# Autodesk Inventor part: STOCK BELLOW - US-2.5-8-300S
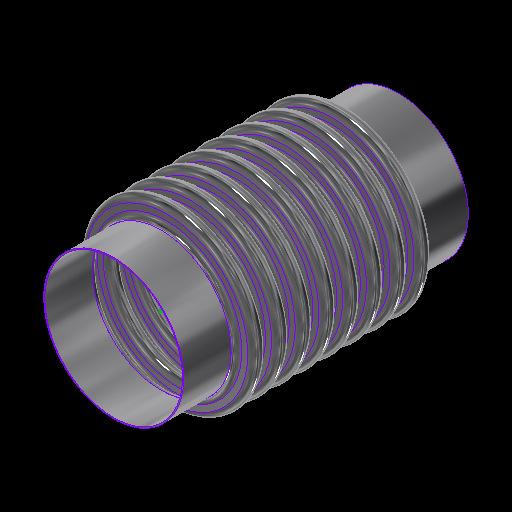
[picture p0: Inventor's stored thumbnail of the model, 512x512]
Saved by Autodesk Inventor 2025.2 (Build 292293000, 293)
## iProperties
Category: 24 GA (0.024 THICK)
RuleStatus: InUse
Created: 2024-01
Part Number: STOCK BELLOW - US-2.5-8-300S
Project: =STOCK BELLOWS: <Stock Number><SFILL>
Material: ASTM A240-304
Description: =STOCK BELLOWS: <Stock Number>, <SID_> I.D., <SOD_> O.D., <SPLY_> PLY, <Category>, <SNET_CONS> CONS.<PITCH_><STANGENT_> TANGENT<SFILL>
Document SubType Name: Sheet Metal
Designer: GS
Stock Number: U.S-2.5-8-300S
Surface Area: 1355.78 cm^2
Volume: 41.0641 cm^3
Sheet Metal Rule: Default
Appearance: STAINLESS STEEL
Mass: 330.865 g
Density: 8.05729 g/cm^3
THK: 0.036
ID: 3.500
OD: 4.250
CONS_: 2
PITCH: 0.500
TANGENT: 0.500
BELLOWS_UPSET: 0.000
d79: 1.000
d82: 1.000
d83: 26.000
d84: 24.000
d174: 8
d214: 8
STHK_: 0.024
SID_: 2.900
SOD_: 3.700
SPITCH_: 0.500
STANGENT__: 1.000
SBELLOWS_UPSET_: 0.000
SDIFF_TAN: 1.000
d252: 2
d275: 2
d287: 0.050
d289: 0.500
d290: 0.000
SOD_NECK: 2 15/16
PLY: 1
PSET: 4.178
PBAR: 1.035
COUNTER: 1.500
NET_TUBE: 3.071
CONS: 2
S_CONS: 0
NET_CONS: 2
ID_M: 88.90 mm
OD_M: 107.95 mm
THK_M: 0.91 mm
ID_U: 3.500 in
OD_U: 4.250 in
THK_U: 0.036 in
TANGENT2: 0.500
TAN_TO_TAN: 1.000 in
d80: 2.571
d81: 10
SID: 2.375
SCONS_: 8
SPITCH: 0.250
STANGENT_: 1.000
SBELLOWS_UPSET: 0.000
SNET_CONS: 8
SS_CONS: 0
SCONS: 8
d190: 8
d191: 1
d192: 1
d193: 8
d194: 0
SIZE: 2.50
PRESSURE: 300
d230: 8
STANGENT: 4.000
SPLY_: 1
d233: 8
d234: 0
d263: 2
d265: 1
d268: 2
d269: 0
d286: 2
d288: 1
d291: 2
d292: 0
SREROLL: 0.750
BLETP: 0.000 ul
PRES_Copy: 85
MATTABLE: 20 GA (0.036 THICK)
PART_NUMBER: U.S-2.5-8-300S
PITCH_: =, <SPITCH_> PITCH,
CFILL: .
SFILL: .
MESH: ,
COMP: 0.77
EXT: 0.39
LAT: 0.30
ANG: 573
ASR: 1441
LSR: 1471
ANSR: 53
PRES: 300
COMPM: 7.7
EXTM: 3.85
LATM: 3.00
ASRM: 252.362
PRESM: 20.684
LSRM: 257.616
ANSRM: 9.282
TEMPMIN: 20
TEMPMAX: 800
TEMPMINM: -7
TEMPMAXM: 427
WEIGHTM: 0.331
WEIGHT: 0.729
Author: GS
Keywords: 20 GA (0.036 THICK)
Comments: =STOCK BELLOW - <STOCK NUMBER>
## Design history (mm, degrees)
sketch "Sketch2"
  geometry: L1 (0, -177.245)-(0, 562.856) reference; L2 (45.364, 0)-(44.45, 0); L3 (48.082, -2.718)-(50.343, -2.718); L4 (48.082, -3.632)-(50.343, -3.632); L5 (50.343, -9.982)-(48.082, -9.982); L6 (50.343, -9.068)-(48.082, -9.068); L7 (45.364, -12.7)-(44.45, -12.7); L8 (48.082, 0)-(48.082, -12.7); L9 (50.343, -6.35)-(53.975, -6.35); L10 (44.45, 0)-(44.45, -12.7); L11 (20.376, 102.841)-(20.376, 101.926); L12 (58.262, 457.127)-(58.262, 349.177); L13 (58.262, 444.427)-(58.262, 336.477); L14 (93.133, -58.817)-(93.133, -71.517); L15 (118.746, -66.401)-(118.746, -66.401); L16 (50.343, -9.068)-(50.343, -9.982); L17 (48.082, -9.068)-(48.082, -9.982); L18 (48.082, -9.525)-(50.343, -9.525); L19 (53.975, 0)-(53.975, -12.7); L20 (-50.343, -9.068)-(-50.343, -9.982); L21 (-50.343, -2.718)-(-48.082, -2.718); L22 (-50.343, -3.632)-(-48.082, -3.632); L23 (-48.082, -9.068)-(-50.343, -9.068); L24 (-50.343, -9.525)-(-48.082, -9.525); L25 (-48.082, -9.982)-(-50.343, -9.982); L26 (-48.082, -9.068)-(-48.082, -9.982); L27 (-44.45, 0.653)-(-44.45, -12.047); L28 (-48.082, -6.35)-(-44.45, -6.35); L29 (-50.343, 0.653)-(-50.343, -12.7); L30 (-53.061, 0)-(-53.975, 0); L31 (-53.975, 0)-(-53.975, -12.7); L32 (-53.061, -12.7)-(-53.975, -12.7); A1 r 2.718 centre (48.082, 0) between (45.364, 0) and (48.082, -2.718); A2 r 3.632 centre (48.082, 0) between (44.45, 0) and (48.082, -3.632); A3 r 3.632 centre (50.343, -6.35) between (50.343, -9.982) and (50.343, -2.718); A4 r 2.718 centre (50.343, -6.35) between (50.343, -9.068) and (50.343, -3.632); A5 r 2.718 centre (48.082, -12.7) between (48.082, -9.982) and (45.364, -12.7); A6 r 3.632 centre (48.082, -12.7) between (48.082, -9.068) and (44.45, -12.7); A7 r 3.175 centre (50.343, -6.35) between (50.343, -9.525) and (53.518, -6.35); A8 r 3.175 centre (48.082, -12.7) between (48.082, -9.525) and (44.907, -12.7); A9 r 2.718 centre (-50.343, -12.7) between (-50.343, -9.982) and (-53.061, -12.7); A10 r 2.718 centre (-48.082, -6.35) between (-48.082, -9.068) and (-48.082, -3.632); A11 r 3.175 centre (-48.082, -6.35) between (-48.082, -9.525) and (-44.907, -6.35); A12 r 3.632 centre (-48.082, -6.35) between (-48.082, -9.982) and (-48.082, -2.718); A13 r 3.175 centre (-50.343, -12.7) between (-50.343, -9.525) and (-53.518, -12.7); A14 r 3.632 centre (-50.343, -12.7) between (-50.343, -9.068) and (-53.975, -12.7); A15 r 2.718 centre (-50.343, 0) between (-53.061, 0) and (-50.343, -2.718); A16 r 3.632 centre (-50.343, 0) between (-53.975, 0) and (-50.343, -3.632); 10 further points
  constraints: 62 end point, 38 point on circle, 20 tangent, 16 centre point, 12 parallel, 9 midpoint, 7 vertical, 6 coincident, 6 concentric, 6 point on line, 4 equal radius, 4 perpendicular, 3 horizontal, 1 collinear, 1 horizontal alignment, 10 other
  dimensions: "THK" = 0.9144 distance of L11.start L11.end; "ID" = 88.9 distance of L11.end point (20.376, 13.026); "OD" = 107.95 distance of L12.start L12.end; "PITCH" = 12.7 distance of L12.start L13.start; "TANGENT" = 12.7 distance of L14.start L14.end; "BELLOWS_UPSET" = 0 distance of L15.start L15.end; "d43" = 88.9 diameter of L10 L1 (= ID); "d44" = 107.95 diameter of L9.end L1 (= OD); "d45" = 0.9144 distance between parallel lines of L5 L6 (computed from THK, PLY); "d46" = 3.6322 radius of A3 (computed from PITCH, THK, PLY); "UPSET_PITCH" = 12.7 distance of L2.end L7.end (derived); "SIDEWALL_ANGLE" = 360 deg dimension on L3 L9 (derived); "CON_GAP" = 5.4356 distance of point (48.082, -9.068) point (48.082, -3.632) (derived); "TAN1" = 4.98728 dimension on A8 (derived); "TAN2" = 4.98728 dimension on A7 (derived); "LEG1" = 2.2606 distance of L18.start L18.end (derived); "d278" = 0.9144 distance between parallel lines of L25 L23 (derived); "d279" = 3.6322 radius of A12 (derived); "d280" = 12.7 distance of L30.end L31.end (derived); "d281" = 360 deg dimension on L21 L28 (derived); "d282" = 5.4356 distance of point (-50.343, -9.068) point (-50.343, -3.632) (derived); "d283" = 4.98728 dimension on A13 (derived); "d284" = 4.98728 dimension on A11 (derived); "d285" = 2.2606 distance of L24.start L24.end (derived); "d293" = 88.9 diameter of L27 L1 (derived); "d294" = 107.95 diameter of L31 L1 (derived)
  node "Sketch Rectangular Pattern1" dims "d31" = 25.4, "ID" = 88.9
  node "Sketch Rectangular Pattern2" dims "d39" = 25.4, "PITCH" = 12.7
revolve "CONS" stored, may be unused: angle "d48" = 90 deg
node "BELLOW MIDPLANE"
pattern_linear "Rectangular Pattern2" dims "d52" = 12.7 (= UPSET_PITCH)
sketch "Sketch5"
  geometry: C1 r 45.364 at (0, 0) reference; C2 r 44.45 at (0, 0) reference
extrude "TANGENT" new body sketch "Sketch5" distance "d53" = 12.7 (= TANGENT); taper "d54" = 0 deg
revolve "SAMETAN" stored, may be unused: angle "d65" = 90 deg
revolve "DIFFTAN" stored, may be unused: angle "d70" = 90 deg
sketch "Sketch9"
  geometry: L1 (53.319, 0)-(-53.319, 0) reference; L2 (0, -17.78)-(0, 17.78) reference; L3 (38.085, 0)-(-38.085, 0); L4 (38.085, -11.906)-(38.085, 11.906); L5 (25.385, -11.906)-(25.385, 11.906); L6 (13.15, 11.906)-(13.15, -11.906); L7 (-25.385, -11.906)-(-25.385, 11.906); L8 (-38.085, -11.906)-(-38.085, 11.906); L9 (37.291, -11.906)-(37.291, 11.906); L10 (38.085, -11.906)-(37.291, -11.906); L11 (38.085, 11.906)-(37.291, 11.906); L12 (13.546, 11.906)-(12.753, 11.906); L13 (12.753, 11.906)-(12.753, -11.906); L14 (12.753, -11.906)-(13.546, -11.906); L15 (13.546, -11.906)-(13.546, 11.906); L16 (-13.546, 11.906)-(-13.546, -11.906); L17 (-13.15, 11.906)-(-13.15, -11.906); L18 (-13.546, -11.906)-(-12.753, -11.906); L19 (-12.753, -11.906)-(-12.753, 11.906); L20 (-12.753, 11.906)-(-13.546, 11.906); L21 (-38.085, -11.906)-(-37.291, -11.906); L22 (-37.291, -11.906)-(-37.291, 11.906); L23 (-37.291, 11.906)-(-38.085, 11.906); L24 (-38.085, 11.906)-(-38.085, -11.906); L25 (38.085, -0.397)-(-38.085, -0.397); L26 (-38.085, -0.397)-(-38.085, 0.397); L27 (-38.085, 0.397)-(38.085, 0.397); L28 (38.085, 0.397)-(38.085, -0.397); L29 (-38.085, 11.906)-(38.085, 11.906); L30 (38.085, 11.906)-(38.085, 12.7); L31 (38.085, 12.7)-(-38.085, 12.7); L32 (-38.085, 12.7)-(-38.085, 11.906); L33 (38.085, -11.906)-(-38.085, -11.906); L34 (-38.085, -11.906)-(-38.085, -12.7); L35 (-38.085, -12.7)-(38.085, -12.7); L36 (38.085, -12.7)-(38.085, -11.906); 30 further points
  constraints: 68 end point, 13 midpoint, 13 parallel, 8 horizontal, 7 perpendicular, 6 equal length, 3 point on line, 2 vertical, 14 other
  dimensions: "d115" = 23.8125 distance of L4.start L4.end (derived); "d116" = 12.7 distance between parallel lines of L4 L5 (derived); "d117" = 12.23516 distance between parallel lines of L5 L6 (derived); "d125" = 38.53427 distance between parallel lines of L7 L6 (derived); "d127" = 12.7 distance between parallel lines of L8 L7 (derived); "d128" = 24.93516 distance between parallel lines of L6 L4 (derived); "d130" = 76.16943 distance between parallel lines of L8 L4 (derived); "RULER_THK" = 0.79375 distance between parallel lines of L4 L9; "d135" = 0.79375 distance of L13.end L14.end (derived); "d138" = 26.29911 distance of L13.end L16.end (derived); "d143" = 0.79375 distance of L22.end L8.end (derived); "d144" = 0.79375 distance between parallel lines of L27 L25 (derived)
extrude "RULER" join sketch "Sketch9" distance "d149" = 0.79375 (derived); taper "d150" = 0 deg
extrude "BARS" join sketch "Sketch9" distance "d151" = 0.79375 (derived); taper "d152" = 0 deg
pattern_linear "Rectangular Pattern4" dims "d155" = 26.29911 (derived)
sketch "Sketch13"
  geometry: L1 (93.149, -52.467)-(93.149, -77.867); L2 (37.44, 0)-(36.83, 0); L3 (37.44, -12.7)-(36.83, -12.7); L4 (43.51, -9.83)-(40.31, -9.83); L5 (43.51, -9.22)-(40.31, -9.22); L6 (43.51, -6.35)-(46.99, -6.35); L7 (40.31, -2.87)-(43.51, -2.87); L8 (40.31, 0)-(40.31, -12.7); L9 (36.83, 0)-(36.83, -12.7); L10 (58.254, -402.451)-(58.254, -496.431); L11 (58.254, -415.151)-(58.254, -509.131); L12 (58.254, -440.551)-(58.254, -534.531); L13 (58.254, -453.251)-(58.254, -547.231); L14 (58.254, -465.951)-(58.254, -559.931); L15 (58.254, -478.651)-(58.254, -572.631); L16 (58.254, -491.351)-(58.254, -585.331); L17 (58.254, -427.851)-(58.254, -521.831); L18 (20.376, 102.536)-(20.376, 101.926); L19 (40.31, -3.48)-(43.51, -3.48); L20 (0, -722.904)-(0, 240.109) reference; L21 (-23.752, 0)-(142.514, 0) reference; A1 r 2.87 centre (40.31, 0) between (37.44, 0) and (40.31, -2.87); A2 r 2.87 centre (40.31, -12.7) between (40.31, -9.83) and (37.44, -12.7); A3 r 3.48 centre (40.31, -12.7) between (40.31, -9.22) and (36.83, -12.7); A4 r 2.87 centre (43.51, -6.35) between (43.51, -9.22) and (43.51, -3.48); A5 r 3.48 centre (43.51, -6.35) between (43.51, -9.83) and (43.51, -2.87); A6 r 3.48 centre (40.31, 0) between (36.83, 0) and (40.31, -3.48); 6 further points; 1 other entity
  constraints: 38 end point, 15 point on circle, 9 tangent, 6 centre point, 6 parallel, 5 vertical alignment, 4 point on line, 4 vertical, 3 coincident, 3 concentric, 2 collinear, 2 equal radius, 1 horizontal, 1 perpendicular, 23 other
  dimensions: "SBELLOWS_UPSET_" = 0 distance of point (118.762, -66.401) point (118.762, -66.401); "STOTAL_THK_BELLOW__" = 0.6096 distance between parallel lines of L4 L5 (derived); "d224" = 3.4798 radius of A5 (derived); "d225" = 12.7 distance of L2.end L3.end (derived); "SSIDEWALL_ANGLE_" = 0 deg angle of L7 L6 (derived); "SSCON_GAP_" = 5.7404 distance of point (40.31, -9.22) point (40.31, -3.48) (derived); "d235" = 73.66 diameter of L9 L20 (derived); "d236" = 93.98 diameter of L6.end L20 (derived)
  node "Sketch Rectangular Pattern4" dims "d228" = 25.4
  node "Sketch Rectangular Pattern5" dims "d229" = 25.4
revolve "SBELLOW" stored, may be unused: angle "d197" = 90 deg
pattern_linear "Rectangular Pattern5" dims "d204" = 12.7 (derived)
revolve "STANGENT" stored, may be unused: angle "d240" = 90 deg
revolve "SSAMETAN" stored, may be unused: angle "d241" = 90 deg
revolve "SDIFFTAN" stored, may be unused: angle "d246" = 90 deg
revolve "INVCON" stored, may be unused: angle "d295" = 90 deg
pattern_linear "Rectangular Pattern6" dims "d298" = 12.7 (derived)
revolve "INVTANGENT" stored, may be unused: angle "d302" = 90 deg
revolve "INVSAMETAN" stored, may be unused: angle "d307" = 90 deg
revolve "INVDIFFTAN" stored, may be unused: angle "d312" = 90 deg
sketch "ID BELLOW MOUNT CALC"
  geometry: L1 (44.45, 0)-(38.1, 0); L2 (38.1, 0)-(38.1, 12.7); L3 (38.1, 12.7)-(44.45, 12.7); L4 (44.45, 12.7)-(44.45, 0); L5 (36.513, 12.7)-(35.598, 12.7); L6 (35.598, 12.7)-(35.598, 0); L7 (35.598, 0)-(36.513, 0); L8 (36.513, 0)-(36.513, 12.7); L9 (0, -2.54)-(0, 15.24) reference; L10 (-8.89, 0)-(53.34, 0) reference; 1 further point
  constraints: 16 end point, 5 parallel, 2 collinear, 2 horizontal, 2 perpendicular
  dimensions: "d314" = 12.7 distance of L5.end L6.end (derived); "d315" = 0.9144 distance of L5.start L5.end (derived); "IG" = 1.5875 distance between parallel lines of L2 L8; "PIPE_OD" = 88.9 diameter of L4 L9; "PIPE_WALL" = 6.35 distance of L2.end L3.end; "ID_MT_BELLOW" = 71.1962 diameter of L6 L9 (derived)
revolve "CFILL" stored, may be unused: angle "d320" = 90 deg
pattern_linear "Rectangular Pattern7" dims "d323" = 12.7 (derived)
revolve "SFILL" stored, may be unused: angle "d324" = 90 deg
pattern_linear "Rectangular Pattern8" dims "d327" = 12.7 (derived)
node "STOCK BELLOW MIDPLANE"
node "BELLOW"
sketch "Sketch6"
  geometry: L1 (-12.7, 45.364)-(0, 45.364); L2 (0, 45.364)-(0, 44.45); L3 (0, 44.45)-(-12.7, 44.45); L4 (-12.7, 44.45)-(-12.7, 45.364); L5 (10.16, 0)-(-60.96, 0) reference; L6 (-38.1, -89.422)-(-38.1, 153.44) reference; 1 further point
  constraints: 8 end point, 2 parallel, 1 horizontal, 1 perpendicular
  dimensions: "d61" = 12.7 distance of L2.end L3.end (derived); "d62" = 0.9144 distance of L1.end L2.end (derived); "d63" = 88.9 diameter of L3 L5 (derived); "d64" = 25.4 distance between parallel lines of L4 L6 (derived)
sketch "Sketch12"
  geometry: 1 further point
sketch "Sketch14"
  geometry: L1 (-25.4, 37.44)-(0, 37.44); L2 (0, 37.44)-(0, 36.83); L3 (0, 36.83)-(-25.4, 36.83); L4 (-25.4, 36.83)-(-25.4, 37.44); L5 (5.08, 0)-(-30.48, 0) reference; L6 (0, -8.89)-(0, 53.34) reference; 1 further point
  constraints: 8 end point, 2 parallel, 1 collinear, 1 horizontal, 1 perpendicular
  dimensions: "d237" = 0.6096 distance of L3.end L1.start (derived); "d238" = 73.66 diameter of L3 L5 (derived); "d239" = 25.4 distance of L1.start L1.end (derived); "SOD_NECK" = 74.8792 diameter of L1 L5 (derived)
sketch "Sketch15"
  geometry: L1 (-8.89, 0)-(53.34, 0) reference; L2 (36.83, -101.6)-(37.44, -101.6); L3 (37.44, -101.6)-(37.44, -127); L4 (37.44, -127)-(36.83, -127); L5 (36.83, -127)-(36.83, -101.6); L6 (0, -154.94)-(0, 40.64) reference; 1 further point
  constraints: 8 end point, 2 parallel, 1 horizontal, 1 perpendicular
  dimensions: "d205" = 25.4 distance of L4.end L2.start (derived); "d206" = 0.6096 distance of L3.end L4.end (derived); "d207" = 73.66 diameter of L5 L6 (derived); "d208" = 101.6 distance between parallel lines of L1 L2 (derived)
node "TANGENT_"
node "SAME_TAN"
sketch "Sketch8"
  geometry: L1 (45.364, -25.4)-(44.45, -25.4); L2 (44.45, -25.4)-(44.45, -38.1); L3 (44.45, -38.1)-(45.364, -38.1); L4 (45.364, -38.1)-(45.364, -25.4); L5 (0, -48.26)-(0, 22.86) reference; L6 (-89.422, 0)-(153.44, 0) reference; 1 further point
  constraints: 8 end point, 2 parallel, 1 horizontal, 1 perpendicular
  dimensions: "d66" = 88.9 diameter of L2 L5 (derived); "TOTAL_THK_BELLOW" = 0.9144 distance of L2.end L3.end (derived); "d68" = 25.4 distance between parallel lines of L1 L6 (derived); "d69" = 12.7 distance of L1.end L2.end (derived)
node "DIFF_TAN"
node "Sketch Rectangular Pattern3" dims "d138" = 26.29911 (derived), "d141" = 25.4
node "SBELLOW_"
node "STANGENT_"
node "SSAME_TAN"
sketch "Sketch16"
  geometry: L1 (37.44, -101.6)-(36.83, -101.6); L2 (36.83, -101.6)-(36.83, -127); L3 (36.83, -127)-(37.44, -127); L4 (37.44, -127)-(37.44, -101.6); L5 (0, -154.94)-(0, 40.64) reference; L6 (-8.89, 0)-(53.34, 0) reference; 1 further point
  constraints: 8 end point, 2 parallel, 1 horizontal, 1 perpendicular
  dimensions: "SDIFF_TAN" = 25.4 distance of L3.end L1.start; "d243" = 0.6096 distance of L2.end L3.end (derived); "d244" = 101.6 distance between parallel lines of L1 L6 (derived); "d245" = 73.66 diameter of L2 L5 (derived)
node "SDIFF_TAN"
body "Solid15"
sketch "Sketch17"
  geometry: L1 (53.975, 12.7)-(53.061, 12.7); L2 (53.061, 12.7)-(53.061, 0); L3 (53.061, 0)-(53.975, 0); L4 (53.975, 0)-(53.975, 12.7); L5 (0, -2.54)-(0, 15.24) reference; L6 (-10.795, 0)-(64.77, 0) reference; 2 further points
  constraints: 8 end point, 2 parallel, 1 horizontal, 1 midpoint, 1 perpendicular, 1 point on line
  dimensions: "INVTANGENT" = 12.7 distance of L3.end L1.start (derived); "d300" = 0.9144 distance of L1.start L1.end (derived); "d301" = 107.95 diameter of L4 L5 (derived)
body "Solid16"
sketch "Sketch18"
  geometry: L1 (53.975, -25.4)-(53.061, -25.4); L2 (53.061, -25.4)-(53.061, -38.1); L3 (53.061, -38.1)-(53.975, -38.1); L4 (53.975, -38.1)-(53.975, -25.4); L5 (-10.795, 0)-(64.77, 0) reference; L6 (0, -48.26)-(0, 22.86) reference; 1 further point
  constraints: 8 end point, 2 parallel, 1 horizontal, 1 perpendicular
  dimensions: "d303" = 25.4 distance between parallel lines of L1 L5 (derived); "d304" = 12.7 distance of L3.end L1.start (derived); "d305" = 0.9144 distance of L2.end L3.end (derived); "d306" = 107.95 diameter of L4 L6 (derived)
body "Solid17"
sketch "Sketch19"
  geometry: L1 (53.975, -25.4)-(53.061, -25.4); L2 (53.061, -25.4)-(53.061, -38.1); L3 (53.061, -38.1)-(53.975, -38.1); L4 (53.975, -38.1)-(53.975, -25.4); L5 (0, -48.26)-(0, 22.86) reference; L6 (-10.795, 0)-(64.77, 0) reference; 1 further point
  constraints: 8 end point, 2 parallel, 1 horizontal, 1 perpendicular
  dimensions: "d308" = 12.7 distance of L1.end L2.end (derived); "d309" = 107.95 diameter of L4 L5 (derived); "d310" = 0.9144 distance of L2.end L3.end (derived); "d311" = 25.4 distance between parallel lines of L1 L6 (derived)
body "Solid18"
body "Solid19"
body "Solid20"
other parameters: "BMPL" = -50.8, "PSET" = 106.1212 (computed from OD, THK, PLY) [user parameter], "PBAR" = 26.29911 (= 0.570796 x PITCH + OD - ID) [user parameter; used in 1 equation term], "COUNTER" = 15 [user parameter], "NET_TUBE" = 77.99823 (computed from CONS_, PBAR, TANGENT) [user parameter], "S_CONS" = 0 [user parameter; used in 1 equation term], "ID_M" = 88.9 (= ID) [user parameter], "OD_M" = 107.95 (= OD) [user parameter], "THK_M" = 0.9144 (= THK) [user parameter], "ID_U" = 88.9 (= ID) [user parameter], "OD_U" = 107.95 (= OD) [user parameter], "THK_U" = 0.9144 (= THK) [user parameter], "D_UNITS" = 0 [user parameter], "TANGENT2" = 12.7 [user parameter], "TAN_TO_TAN" = 25.4 [user parameter], "OD_NECK" = 90.7288 [user parameter], "d79" = 25.4, "d80" = 65.29823 [user parameter], "d82" = 25.4, "d83" = 660.4, "d84" = 609.6, "sa_0" = 4, "FRAME_THK" = 0.79375 [user parameter], "CON_FLAT" = 12.23516 [user parameter], "SID" = 60.325 [user parameter], "SPITCH" = 6.35 [user parameter], "STANGENT_" = 25.4 [user parameter], "SBELLOWS_UPSET" = 0 [user parameter], "SS_CONS" = 0 [user parameter], "STAN_TO_TAN_" = 101.6 [user parameter], "d100" = 0.6096 [user parameter], "d191" = 25.4 [user parameter], "d194" = 0 [user parameter], "STANGENT" = 101.6 [user parameter], "d234" = 0 [user parameter], "SUPSET_PITCH_" = 12.7 [user parameter], "d269" = 0 [user parameter], "d287" = 1.27, "d289" = 12.7, "d290" = 0, "d292" = 0 [user parameter], "Thickness" = 3.048 (derived), "KFactor" = 4.4, "BendRadius" = 3.048 (derived), "BendReliefWidth" = 3.048 (derived), "BendReliefDepth" = 1.524 (derived), "CornerReliefSize" = 12.192 (derived), "SeamGap" = 0.00508, "MinimumRemnant" = 6.096 (derived), "TransitionRadius" = 3.048 (derived), "JacobiRadiusSize" = 3.048 (derived), "GapSize" = 3.048 (derived), "SREROLL" = 19.05 [user parameter], "CUR_STK_PITCH" = 12.7 [user parameter], "d328" = -50.8 (derived), "ASR" = 14410 [user parameter], "LSR" = 14710 [user parameter], "BLETP" = 0 [user parameter], "ASRM" = 2523.6233 [user parameter], "PRESM" = 206.83949 [user parameter], "LSRM" = 2576.1623 [user parameter], "ANSRM" = 92.8189 [user parameter], "TEMPMIN" = 2664.83333 [user parameter], "TEMPMAX" = 6998.16667 [user parameter], "TEMPMINM" = 2664.83333 [user parameter], "TEMPMAXM" = 6998.16667 [user parameter], "WEIGHT" = 3.30865 [user parameter], "WEIGHTM" = 0.00331 [user parameter]
